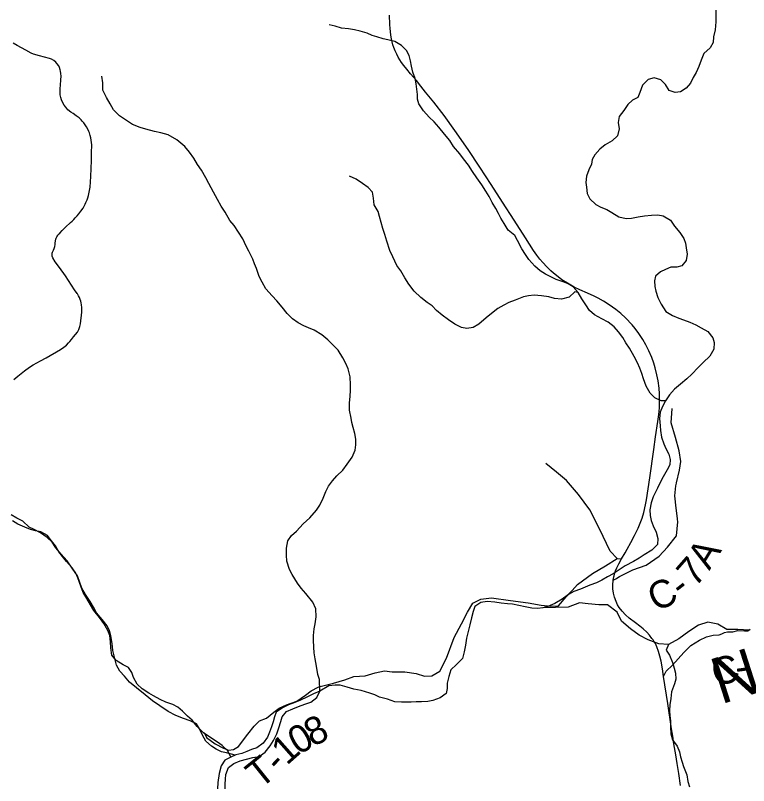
# Model space of a CAD drawing. Extents: x 0 to 34, y 0 to 22.
# Drawn here: x 3.746 to 5.252, y 18.512 to 20.093 of the extents above; entities that cross this region are included whole.
import ezdxf

# ---------------------------------------------------------------- set-up
doc = ezdxf.new("R2010")
doc.units = 0
for name, color, linetype in [('GM_X_County_Road', 7, 'Continuous'), ('GM_X_County_Road_Text', 7, 'Continuous'), ('GM_X_Major_River', 7, 'Continuous'), ('GM_X_Minor_River', 7, 'Continuous'), ('GM_X_Minor_River_Text', 7, 'Continuous'), ('GM_X_State_Route', 7, 'Continuous'), ('GM_X_Township_Road', 7, 'Continuous'), ('GM_X_Township_Road_Text', 7, 'Continuous')]:
    doc.layers.add(name, color=color, linetype=linetype)

msp = doc.modelspace()

# ---------------------------------------------------------------- linework, layer by layer
at = {"layer": 'GM_X_County_Road'}
for points in [[(3.8738, 19.5212), (3.8733, 19.522), (3.8678, 19.5297), (3.8488, 19.5588), (3.837, 19.5758), (3.8281, 19.5874), (3.8232, 19.5951), (3.8218, 19.5985), (3.8216, 19.6006), (3.8215, 19.6029), (3.8217, 19.605), (3.8224, 19.6073), (3.8243, 19.611), (3.8259, 19.6148), (3.8266, 19.6166), (3.827, 19.6185), (3.8277, 19.6227), (3.828, 19.6257), (3.8286, 19.6303), (3.8292, 19.6335), (3.8302, 19.6359), (3.8312, 19.6385), (3.8325, 19.6405), (3.8343, 19.643), (3.8373, 19.6463), (3.8419, 19.6514), (3.8493, 19.6585), (3.8594, 19.6678), (3.8627, 19.6707), (3.8662, 19.6742), (3.8692, 19.6774), (3.8731, 19.6817), (3.8766, 19.686), (3.8807, 19.6911), (3.8851, 19.6974), (3.8881, 19.7026), (3.8892, 19.7057), (3.8911, 19.7087), (3.8936, 19.7147), (3.895, 19.7189), (3.8962, 19.7231), (3.898, 19.7301), (3.8998, 19.7408), (3.901, 19.7627), (3.9025, 19.795), (3.9026, 19.8108), (3.903, 19.8276), (3.9027, 19.832), (3.9018, 19.8373), (3.9009, 19.842), (3.8996, 19.8467), (3.8984, 19.8517), (3.8973, 19.8549), (3.8949, 19.8596), (3.8924, 19.8642), (3.8867, 19.8724), (3.8836, 19.8759), (3.8811, 19.8787), (3.877, 19.8826), (3.8713, 19.887), (3.8647, 19.8915), (3.8599, 19.8945), (3.854, 19.8995), (3.8495, 19.9044), (3.8462, 19.9089), (3.8433, 19.9139), (3.8408, 19.9195), (3.8392, 19.9247), (3.8381, 19.93), (3.838, 19.9346), (3.838, 19.9427), (3.8388, 19.9501), (3.8396, 19.9606), (3.8399, 19.9683), (3.8396, 19.9737), (3.8388, 19.9789), (3.838, 19.9815), (3.8368, 19.986), (3.8351, 19.9897), (3.8316, 19.9946), (3.8291, 19.9972), (3.8248, 20.0006), (3.8206, 20.0033), (3.8163, 20.0048), (3.8059, 20.0075), (3.7957, 20.0098), (3.7834, 20.0133), (3.7783, 20.0156), (3.7677, 20.0217), (3.7501, 20.0312), (3.7416, 20.0362)], [(3.7429, 19.3456), (3.7509, 19.3528), (3.7646, 19.3634), (3.775, 19.3707), (3.7827, 19.3756), (3.7977, 19.3837), (3.8094, 19.3903), (3.8385, 19.4071), (3.8458, 19.4121), (3.8509, 19.4163), (3.8555, 19.4209), (3.858, 19.4237), (3.8615, 19.4281), (3.8656, 19.4331), (3.8696, 19.4378), (3.8734, 19.4429), (3.8764, 19.4482), (3.8785, 19.4545), (3.88, 19.4602), (3.8814, 19.4719), (3.8818, 19.4767), (3.8823, 19.4845), (3.8825, 19.4895), (3.8824, 19.4933), (3.882, 19.4991), (3.8813, 19.5031), (3.8806, 19.5064), (3.8793, 19.5101), (3.8778, 19.5142), (3.8759, 19.5176), (3.8738, 19.5212)], [(5.1036, 19.1337), (5.1095, 19.1595), (5.1123, 19.177), (5.109, 19.1994), (5.1012, 19.2268), (5.0923, 19.2568), (5.0948, 19.2864)], [(5.1057, 19.0602), (5.1029, 19.0813), (5.1001, 19.1068), (5.1021, 19.1273), (5.1034, 19.1329), (5.1036, 19.1337)], [(4.9808, 18.9376), (4.9863, 18.9415), (5.0141, 18.9546), (5.0415, 18.9647), (5.0682, 18.9831), (5.085, 19.0016), (5.1033, 19.0247), (5.1065, 19.0535), (5.1059, 19.0586), (5.1057, 19.0602)], [(4.9734, 18.9337), (4.9787, 18.9362), (4.9808, 18.9376)], [(5.0771, 18.7359), (5.0824, 18.747), (5.095, 18.7591), (5.1188, 18.7855), (5.1332, 18.7995), (5.151, 18.8107), (5.1651, 18.8176), (5.1786, 18.8207), (5.1914, 18.8217), (5.1968, 18.8236), (5.2023, 18.8266), (5.208, 18.8277), (5.2189, 18.8279), (5.2297, 18.8303), (5.2433, 18.8296), (5.2497, 18.8294), (5.2548, 18.833)]]:
    msp.add_lwpolyline(points, dxfattribs=at)
at = {"layer": 'GM_X_Major_River'}
for points in [[(5.1846, 20.104), (5.1846, 20.0926), (5.1843, 20.0801), (5.1831, 20.0638), (5.1797, 20.049), (5.179, 20.0376), (5.1725, 20.0262), (5.1597, 20.0148), (5.1544, 20.0012), (5.1495, 19.9883), (5.1438, 19.9762), (5.1377, 19.9655), (5.1321, 19.9542), (5.1234, 19.9439), (5.112, 19.9363), (5.1007, 19.9348), (5.0886, 19.9386), (5.0807, 19.9511), (5.0716, 19.961), (5.058, 19.9647), (5.0455, 19.9617), (5.0338, 19.9496), (5.0281, 19.9348), (5.0239, 19.9249), (5.0134, 19.9188), (5.0035, 19.9105), (4.9956, 19.8976), (4.9858, 19.8854), (4.9835, 19.8729), (4.9858, 19.86), (4.9827, 19.8456), (4.9718, 19.8354), (4.957, 19.8274), (4.9464, 19.8187), (4.9362, 19.8069), (4.9302, 19.7974), (4.929, 19.7879), (4.9234, 19.7762), (4.9188, 19.7633), (4.9177, 19.7504), (4.9188, 19.7402), (4.9203, 19.7276), (4.9256, 19.7166), (4.9381, 19.7049), (4.9483, 19.6996), (4.9604, 19.6943), (4.9706, 19.6886), (4.9853, 19.6795), (5.0001, 19.6761), (5.0114, 19.6769), (5.0246, 19.6799), (5.0379, 19.6818), (5.0522, 19.6833), (5.0655, 19.6837)], [(5.0655, 19.6837), (5.0764, 19.6818), (5.0912, 19.6724), (5.0995, 19.6606), (5.1101, 19.6477), (5.1184, 19.6352), (5.1218, 19.6257), (5.1233, 19.6162), (5.1252, 19.603), (5.1237, 19.5897), (5.1142, 19.5787), (5.104, 19.576), (5.0919, 19.5764), (5.0813, 19.5718), (5.0707, 19.5669), (5.0605, 19.5578), (5.0583, 19.5479), (5.059, 19.5366), (5.0609, 19.5267), (5.0654, 19.5138), (5.0719, 19.5005), (5.0817, 19.485), (5.0953, 19.477), (5.1081, 19.4713), (5.118, 19.4683), (5.1308, 19.4634), (5.1433, 19.4581), (5.1543, 19.452), (5.1682, 19.4441), (5.1784, 19.4312), (5.1811, 19.4217), (5.1799, 19.408), (5.172, 19.3936), (5.1584, 19.3803), (5.1478, 19.3701), (5.1353, 19.3568), (5.1251, 19.3473), (5.1119, 19.3363), (5.0994, 19.3261), (5.0892, 19.3143), (5.0809, 19.3018), (5.0748, 19.29), (5.0699, 19.2786), (5.0684, 19.2657), (5.0699, 19.2506), (5.0707, 19.2407), (5.0729, 19.2274), (5.0775, 19.2138), (5.0816, 19.2039), (5.088, 19.1922), (5.0903, 19.1812), (5.0896, 19.1702), (5.0843, 19.1599), (5.0759, 19.1455), (5.0684, 19.1318), (5.0642, 19.1223), (5.0559, 19.1049), (5.0514, 19.0924), (5.0491, 19.078), (5.0495, 19.0666), (5.0517, 19.0563), (5.0555, 19.045), (5.0616, 19.0321), (5.065, 19.0195), (5.0642, 19.007), (5.0532, 18.9956), (5.037, 18.9858), (5.0268, 18.9789), (5.015, 18.9721), (4.9984, 18.963), (4.9856, 18.9546), (4.9738, 18.9467), (4.9621, 18.9406), (4.9504, 18.9337), (4.9391, 18.9284), (4.9258, 18.9231), (4.9065, 18.9155), (4.8929, 18.9102), (4.882, 18.9045), (4.8687, 18.895), (4.8536, 18.8859), (4.8396, 18.8794), (4.8291, 18.8771), (4.8188, 18.8756), (4.8068, 18.8764), (4.7931, 18.879), (4.7795, 18.882), (4.7667, 18.8843), (4.7569, 18.8854), (4.7436, 18.8866), (4.7308, 18.8885), (4.7149, 18.8896), (4.7017, 18.8881), (4.6896, 18.8793), (4.6858, 18.8695), (4.6828, 18.8566), (4.6794, 18.8418), (4.6756, 18.8281), (4.6725, 18.8148), (4.6703, 18.8004), (4.6676, 18.7864)], [(4.6676, 18.7864), (4.6642, 18.7727), (4.6517, 18.7609), (4.6404, 18.7499), (4.6359, 18.7359), (4.6325, 18.7222), (4.6325, 18.7116), (4.6306, 18.7013), (4.6181, 18.6922), (4.6034, 18.6865), (4.5931, 18.6846), (4.5799, 18.6839), (4.569, 18.6842), (4.5587, 18.6831), (4.5489, 18.6835), (4.5387, 18.6831), (4.5255, 18.6838), (4.51, 18.6891), (4.4941, 18.6933), (4.4839, 18.6982), (4.4737, 18.7016), (4.4559, 18.7073), (4.4412, 18.7096), (4.4272, 18.7137), (4.4128, 18.7179), (4.403, 18.7183), (4.3894, 18.7168), (4.3713, 18.7061)], [(4.3713, 18.7061), (4.3584, 18.7004), (4.3444, 18.6932), (4.3319, 18.6871), (4.3199, 18.6826), (4.3066, 18.6776), (4.2945, 18.6719), (4.2813, 18.6624), (4.2779, 18.6529), (4.2756, 18.6431), (4.2718, 18.6328), (4.2681, 18.6214), (4.2635, 18.6116), (4.2552, 18.599), (4.2416, 18.5895), (4.231, 18.5861), (4.2212, 18.5819), (4.2113, 18.5781), (4.1989, 18.5751), (4.1887, 18.5701), (4.1762, 18.5641), (4.169, 18.5523), (4.1648, 18.5371), (4.1618, 18.5181), (4.1611, 18.5056)], [(4.1766, 18.5052), (4.1766, 18.5151), (4.1777, 18.525), (4.1781, 18.5345), (4.1834, 18.5489), (4.1947, 18.5576), (4.2079, 18.5626), (4.2208, 18.5664), (4.2336, 18.5694), (4.2469, 18.5717), (4.259, 18.5804), (4.2696, 18.5933), (4.276, 18.6044), (4.2832, 18.618), (4.287, 18.6306), (4.2911, 18.6435), (4.2941, 18.6529), (4.3028, 18.6643), (4.3157, 18.6697), (4.3274, 18.6742), (4.3406, 18.6788), (4.3527, 18.683), (4.3652, 18.6925), (4.3713, 18.7061)]]:
    msp.add_lwpolyline(points, dxfattribs=at)
at = {"layer": 'GM_X_Minor_River'}
for points in [[(5.0809, 19.3018), (5.0722, 19.3018), (5.0593, 19.3078), (5.0495, 19.3173), (5.0416, 19.3317), (5.0355, 19.3473), (5.0321, 19.3579), (5.028, 19.3689), (5.0235, 19.3799), (5.0166, 19.3932), (5.0072, 19.4098), (4.9996, 19.4212), (4.9932, 19.4318), (4.9842, 19.4432), (4.9755, 19.4538), (4.963, 19.4633), (4.9505, 19.4705), (4.935, 19.4785), (4.9252, 19.4872), (4.9176, 19.4989), (4.9093, 19.5114), (4.9014, 19.5243), (4.8916, 19.5357), (4.881, 19.5418), (4.8708, 19.5463), (4.8568, 19.5512), (4.8466, 19.5558), (4.8345, 19.5622), (4.8239, 19.5687), (4.8129, 19.5785), (4.8005, 19.5918), (4.7933, 19.6024), (4.7861, 19.6142), (4.777, 19.6309), (4.7714, 19.6411), (4.7582, 19.6525), (4.7495, 19.6661), (4.743, 19.6771), (4.7381, 19.6866), (4.7328, 19.6964), (4.7253, 19.7093), (4.7189, 19.7215), (4.7124, 19.7321), (4.7037, 19.745), (4.6939, 19.7598), (4.6849, 19.7727), (4.6762, 19.7855), (4.6663, 19.7988), (4.6588, 19.809), (4.6459, 19.8238), (4.6384, 19.836), (4.627, 19.8496), (4.6153, 19.8636), (4.6059, 19.8746), (4.596, 19.8841), (4.5843, 19.897), (4.5745, 19.9118), (4.5715, 19.9213), (4.5715, 19.9307), (4.5707, 19.9417), (4.5692, 19.9527), (4.567, 19.9634), (4.5624, 19.9763), (4.5598, 19.9891), (4.5575, 20.0001), (4.5545, 20.0108), (4.5492, 20.021), (4.5386, 20.0312), (4.525, 20.0396), (4.511, 20.0426), (4.5012, 20.0452), (4.4884, 20.0494), (4.4785, 20.0521), (4.4683, 20.0566), (4.454, 20.0604), (4.4422, 20.0634), (4.4301, 20.0657), (4.4154, 20.0672), (4.4026, 20.071), (4.3901, 20.0736)], [(3.933, 19.9243), (3.9259, 19.9399), (3.9255, 19.9547), (3.924, 19.9683)], [(4.3713, 18.7061), (4.3705, 18.73), (4.3671, 18.7403), (4.3641, 18.7573), (4.3618, 18.7725), (4.3599, 18.7847), (4.3588, 18.7964), (4.3581, 18.8108), (4.3581, 18.8203), (4.3599, 18.8336), (4.3618, 18.8439), (4.3637, 18.8587), (4.363, 18.875), (4.3566, 18.8883), (4.3422, 18.9065), (4.3328, 18.9175), (4.3252, 18.9273), (4.3142, 18.9451), (4.3093, 18.9554), (4.3037, 18.9725), (4.3025, 18.985), (4.3025, 18.9994), (4.3056, 19.0142), (4.3131, 19.0252), (4.3233, 19.0343), (4.3369, 19.0495), (4.3509, 19.0616), (4.3645, 19.0776), (4.371, 19.0874), (4.3778, 19.1019), (4.3834, 19.1155), (4.3891, 19.1265), (4.3971, 19.1375), (4.4065, 19.1482), (4.4186, 19.1596), (4.4277, 19.1721), (4.4375, 19.1861), (4.4436, 19.2005), (4.4455, 19.2112), (4.4451, 19.2233), (4.4428, 19.2347), (4.4398, 19.2468), (4.4371, 19.2571), (4.4353, 19.2665), (4.4319, 19.2825), (4.4322, 19.298), (4.4338, 19.3109), (4.4341, 19.3238), (4.4341, 19.3344), (4.4334, 19.3511), (4.4292, 19.3674), (4.4243, 19.3788), (4.4187, 19.3898), (4.4088, 19.4057), (4.3986, 19.4164), (4.388, 19.4273), (4.3752, 19.4372), (4.3593, 19.4467), (4.348, 19.452), (4.3382, 19.4561), (4.3268, 19.4618), (4.3151, 19.4702), (4.3041, 19.4808), (4.2936, 19.4944), (4.283, 19.5069), (4.2735, 19.5172), (4.2607, 19.532), (4.2528, 19.5452), (4.2467, 19.557), (4.241, 19.5733), (4.2373, 19.5828), (4.2335, 19.5926), (4.2255, 19.6089), (4.2203, 19.6196), (4.2131, 19.6347), (4.204, 19.6484), (4.1957, 19.6616), (4.1866, 19.6723), (4.1768, 19.6893), (4.1685, 19.7018), (4.1609, 19.7151), (4.153, 19.7303), (4.1436, 19.7481), (4.1375, 19.7595), (4.1284, 19.7754), (4.1201, 19.7868), (4.1126, 19.7997), (4.1039, 19.8122), (4.094, 19.8243), (4.0774, 19.8379), (4.06, 19.8482), (4.0449, 19.8523), (4.0317, 19.855), (4.0139, 19.8595), (4.0022, 19.8629), (3.9867, 19.869), (3.9746, 19.877), (3.9599, 19.8868), (3.9478, 19.8993), (3.941, 19.9118), (3.933, 19.9243)], [(4.9014, 19.5243), (4.8946, 19.5259), (4.8829, 19.5145), (4.8674, 19.5103), (4.8534, 19.5122), (4.8417, 19.5152), (4.8265, 19.5175), (4.811, 19.519), (4.7997, 19.5175), (4.7895, 19.5152), (4.7725, 19.5087), (4.7596, 19.5034), (4.7487, 19.4981), (4.737, 19.4916), (4.7271, 19.4837), (4.7131, 19.4723), (4.698, 19.4594), (4.6859, 19.4525), (4.6731, 19.4503), (4.6621, 19.4521), (4.6481, 19.4593), (4.6353, 19.4684), (4.6224, 19.4779), (4.6111, 19.487), (4.6016, 19.4969), (4.5918, 19.5037), (4.5786, 19.5139), (4.565, 19.5272), (4.554, 19.5412), (4.5461, 19.5541), (4.5374, 19.5685), (4.5295, 19.5799), (4.5208, 19.5973), (4.5151, 19.6106), (4.509, 19.6296), (4.5049, 19.6432), (4.5007, 19.6557), (4.497, 19.6679), (4.4939, 19.6804), (4.4909, 19.6906), (4.483, 19.7043), (4.4815, 19.7179), (4.4792, 19.7301), (4.4705, 19.7399), (4.4588, 19.7479), (4.4456, 19.757), (4.432, 19.7634)], [(4.1976, 18.5745), (4.1797, 18.5793), (4.1691, 18.5812), (4.1585, 18.587), (4.1487, 18.5931), (4.137, 18.603), (4.1306, 18.6155), (4.1242, 18.6284), (4.1178, 18.6387), (4.1053, 18.6452), (4.091, 18.6498), (4.0755, 18.6556), (4.06, 18.6643), (4.043, 18.6754), (4.0275, 18.6857), (4.0124, 18.6983), (3.9946, 18.7128), (3.9806, 18.7242), (3.9701, 18.7368), (3.9603, 18.7467), (3.9535, 18.7592), (3.946, 18.7892), (3.9449, 18.804), (3.9419, 18.8196), (3.9393, 18.8295), (3.9348, 18.8397), (3.9246, 18.853), (3.9125, 18.8667), (3.9069, 18.8785), (3.8997, 18.8899), (3.8899, 18.904), (3.8824, 18.9173), (3.8782, 18.9291), (3.8737, 18.9424), (3.8643, 18.9561), (3.8526, 18.9736), (3.8405, 18.9869), (3.8292, 18.9998), (3.8217, 19.0116), (3.8111, 19.0212), (3.7979, 19.0311), (3.7846, 19.0376), (3.7748, 19.0425), (3.7616, 19.0547), (3.7491, 19.0608), (3.7374, 19.0677)], [(4.1887, 18.5701), (4.1826, 18.5834), (4.1709, 18.594), (4.1611, 18.6009), (4.1478, 18.61), (4.1324, 18.6206), (4.1191, 18.6331), (4.1093, 18.646), (4.0995, 18.6547), (4.0893, 18.6646), (4.0794, 18.6729), (4.0696, 18.6786), (4.0549, 18.6835), (4.0435, 18.6885), (4.0299, 18.6964), (4.0201, 18.7017), (4.0065, 18.7108), (3.9959, 18.7199), (3.9884, 18.7336), (3.9853, 18.7442), (3.9782, 18.7541), (3.9672, 18.7598), (3.9528, 18.7685), (3.9445, 18.7799), (3.9419, 18.795), (3.9415, 18.8072), (3.94, 18.8201), (3.9362, 18.8307), (3.9275, 18.8447), (3.9188, 18.8572), (3.9075, 18.8717), (3.9003, 18.8834), (3.8931, 18.8963), (3.8852, 18.9085), (3.8814, 18.9191), (3.878, 18.9286), (3.8746, 18.9384), (3.8701, 18.9479), (3.8629, 18.9589), (3.8508, 18.9722), (3.8429, 18.982), (3.8357, 18.9919), (3.8285, 19.0044), (3.8206, 19.0147), (3.8119, 19.0253), (3.7983, 19.0332), (3.7877, 19.0347), (3.7771, 19.0378), (3.7654, 19.0423), (3.751, 19.0488), (3.7405, 19.0552)], [(5.2527, 18.8311), (5.2292, 18.8323), (5.2072, 18.8323), (5.1887, 18.8437), (5.1679, 18.8475), (5.149, 18.8415), (5.1289, 18.8286), (5.1084, 18.8134), (5.0868, 18.8016), (5.0671, 18.8027), (5.0452, 18.8111), (5.027, 18.821), (5.0093, 18.8336), (4.9907, 18.8492), (4.9817, 18.8683), (4.9617, 18.8831), (4.9439, 18.8831), (4.9223, 18.885), (4.9041, 18.8873), (4.8808, 18.8786), (4.8291, 18.8771)], [(5.0868, 18.8016), (5.0823, 18.79), (5.0895, 18.7798), (5.0955, 18.7646), (5.0985, 18.7532), (5.1012, 18.743), (5.1019, 18.7308), (5.0993, 18.721), (5.0932, 18.7046), (5.0917, 18.6906), (5.0902, 18.6781), (5.0891, 18.6659), (5.0902, 18.6549), (5.091, 18.6451), (5.091, 18.6321), (5.0917, 18.6185), (5.0951, 18.6056), (5.1046, 18.5927), (5.1098, 18.5813), (5.1117, 18.5711), (5.1151, 18.5604), (5.1182, 18.5509), (5.1246, 18.5342), (5.1268, 18.5206), (5.1299, 18.5092)]]:
    msp.add_lwpolyline(points, dxfattribs=at)
at = {"layer": 'GM_X_State_Route'}
for points in [[(5.03, 19.4342), (5.0262, 19.4398), (5.0184, 19.4502), (5.0122, 19.4578), (4.999, 19.4721), (4.9894, 19.4809), (4.9788, 19.4895), (4.9651, 19.4992), (4.9539, 19.5063), (4.9427, 19.5123), (4.9342, 19.5164), (4.9208, 19.5226), (4.9048, 19.5296), (4.8935, 19.5352), (4.8797, 19.5431), (4.8683, 19.5505), (4.8571, 19.559), (4.8509, 19.5638), (4.8453, 19.569), (4.8373, 19.5767), (4.8288, 19.5859), (4.8231, 19.5929), (4.817, 19.6007), (4.8102, 19.6105), (4.7934, 19.6365), (4.7701, 19.6727), (4.7462, 19.7097), (4.723, 19.7458), (4.7001, 19.7814), (4.6758, 19.8179), (4.6487, 19.8567), (4.6265, 19.8876), (4.6053, 19.9147), (4.5884, 19.9355), (4.5787, 19.9478), (4.5694, 19.9593), (4.5644, 19.9654), (4.5577, 19.9733), (4.5499, 19.983), (4.5439, 19.9903), (4.539, 19.9967), (4.5357, 20.0017), (4.5324, 20.0072), (4.5292, 20.0133), (4.5258, 20.0206), (4.5233, 20.0274), (4.5213, 20.0325), (4.5196, 20.0385), (4.5182, 20.0448), (4.5169, 20.0528), (4.5162, 20.0601), (4.5156, 20.0661), (4.5153, 20.0743), (4.5146, 20.0938)], [(5.1118, 18.5119), (5.1082, 18.5365), (5.1048, 18.5574), (5.1019, 18.5751), (5.0984, 18.5976), (5.0961, 18.6136), (5.0935, 18.6282), (5.0856, 18.6804), (5.0771, 18.7359), (5.0746, 18.7517), (5.072, 18.7672), (5.0695, 18.7775), (5.0666, 18.7875), (5.0633, 18.7968), (5.0602, 18.8035), (5.0573, 18.8084), (5.0557, 18.811), (5.0532, 18.8142), (5.0483, 18.8207), (5.0429, 18.827), (5.0353, 18.8341), (5.0286, 18.8395), (5.0192, 18.8464), (5.0067, 18.8556), (4.9986, 18.8627), (4.992, 18.87), (4.9861, 18.8774), (4.9826, 18.8831), (4.9795, 18.8901), (4.9763, 18.8989), (4.9742, 18.9067), (4.9726, 18.9159), (4.9725, 18.9231), (4.9734, 18.9337), (4.9746, 18.9403), (4.9753, 18.9428), (4.977, 18.9489), (4.9785, 18.953), (4.981, 18.9587), (4.9854, 18.9674), (4.9909, 18.9778), (4.9979, 18.9899), (5.002, 18.9972), (5.01, 19.0112), (5.0174, 19.0254), (5.0247, 19.0403), (5.0292, 19.0507), (5.0328, 19.061), (5.0365, 19.0729), (5.0401, 19.0885), (5.0419, 19.0985), (5.0485, 19.1438), (5.0568, 19.2021), (5.0605, 19.2279), (5.065, 19.2592), (5.067, 19.2739), (5.0685, 19.2876), (5.0689, 19.303), (5.0684, 19.3159), (5.0677, 19.3278), (5.066, 19.3426), (5.0635, 19.3554), (5.0597, 19.3697), (5.057, 19.3793), (5.0527, 19.391), (5.0468, 19.4046), (5.0405, 19.4169), (5.0343, 19.4279), (5.03, 19.4342)]]:
    msp.add_lwpolyline(points, dxfattribs=at)
at = {"layer": 'GM_X_Township_Road'}
for points in [[(4.9349, 19.0599), (4.9258, 19.0782), (4.9025, 19.1095), (4.8776, 19.1381), (4.8569, 19.1554), (4.835, 19.173)], [(4.9815, 18.9784), (4.9673, 18.9932), (4.9453, 19.039), (4.9366, 19.0564), (4.9349, 19.0599)], [(4.8896, 18.9126), (4.9005, 18.9245), (4.931, 18.9471), (4.958, 18.9629), (4.9815, 18.9784), (4.9909, 18.9778)], [(4.3694, 18.715), (4.399, 18.7221), (4.4225, 18.7291), (4.4412, 18.7362), (4.4643, 18.7376), (4.4852, 18.7436), (4.5042, 18.7473), (4.5201, 18.7453), (4.5459, 18.7455), (4.569, 18.7423), (4.586, 18.7365), (4.6012, 18.7372), (4.6176, 18.7469), (4.631, 18.7738), (4.6472, 18.8159), (4.6622, 18.8443), (4.6741, 18.8682), (4.6852, 18.8863), (4.702, 18.895), (4.724, 18.8975), (4.7626, 18.8919), (4.7987, 18.8875), (4.8259, 18.8824), (4.8456, 18.88), (4.8612, 18.8807), (4.8772, 18.8992), (4.8841, 18.9067), (4.8896, 18.9126)], [(4.134, 18.6211), (4.1385, 18.6104), (4.1562, 18.5978), (4.1732, 18.5889), (4.1835, 18.5847), (4.1941, 18.5858), (4.2044, 18.5922), (4.2235, 18.6175), (4.2365, 18.6338), (4.2476, 18.6447), (4.2616, 18.6503), (4.2769, 18.6628), (4.2879, 18.6711), (4.3028, 18.6778), (4.3237, 18.6853), (4.3416, 18.6977), (4.3534, 18.7064), (4.3676, 18.7141), (4.3694, 18.715)]]:
    msp.add_lwpolyline(points, dxfattribs=at)

# ---------------------------------------------------------------- texts
at = {"layer": 'GM_X_County_Road_Text'}
for s, rotation, p in [('A', 58.5244, (5.171, 18.9523)), ('7', 48.781, (5.1417, 18.9175)), ('C', 25.982, (5.0619, 18.8677)), ('-', 38.0577, (5.1149, 18.8951)), ('C', 15.5623, (5.1845, 18.7145)), ('-', 7.3477, (5.2274, 18.7266))]:
    msp.add_text(s, height=0.0568, rotation=rotation, dxfattribs=at).set_placement(p)
at = {"layer": 'GM_X_Minor_River_Text'}
msp.add_text('Norris', height=0.0947, rotation=17.7682, dxfattribs=at).set_placement((5.1944, 18.6783))
at = {"layer": 'GM_X_Township_Road_Text'}
for s, rotation, p in [('8', 26.0821, (4.3563, 18.5908)), ('0', 30.1268, (4.327, 18.5737)), ('1', 41.4992, (4.3032, 18.5522)), ('T', 38.755, (4.2487, 18.5039)), ('-', 46.5359, (4.2881, 18.5362))]:
    msp.add_text(s, height=0.0568, rotation=rotation, dxfattribs=at).set_placement(p)

doc.saveas('drawing.dxf')
